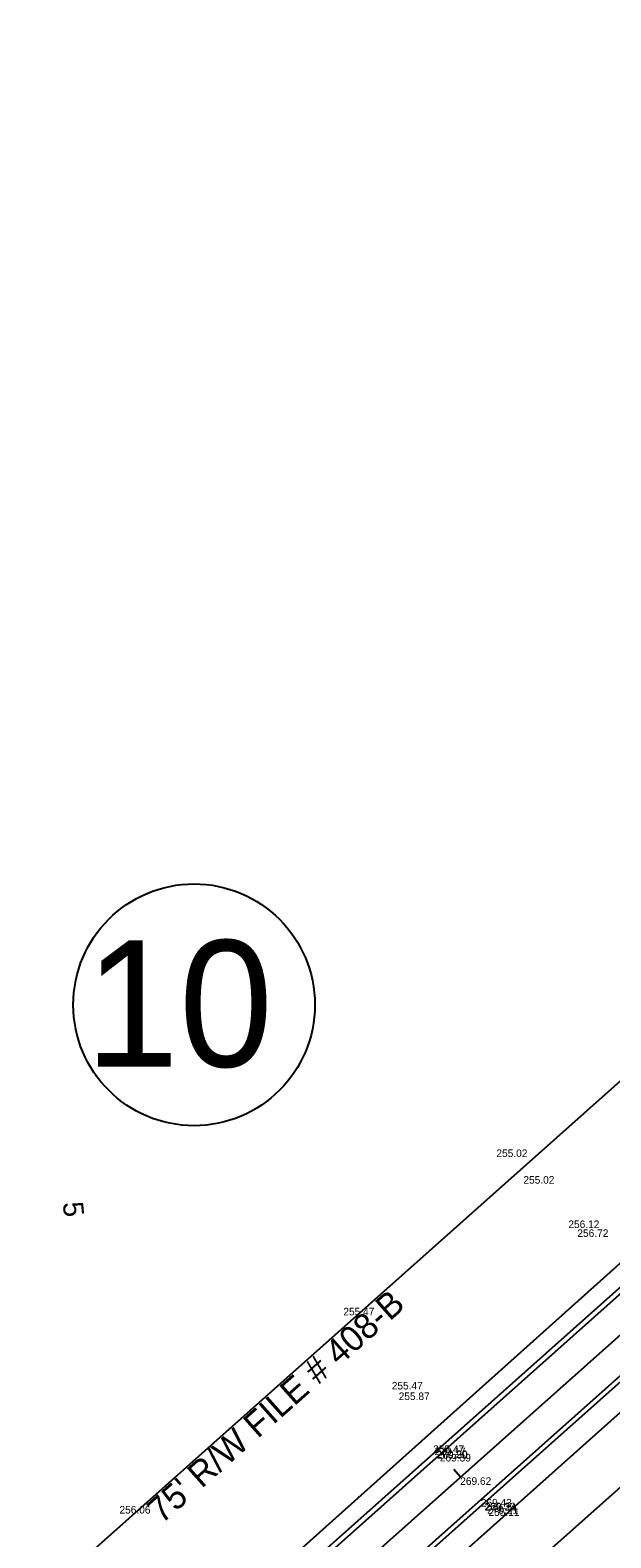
# Model space of a CAD drawing. Extents: x 49683 to 58852, y 49525 to 54803.
# Drawn here: x 53645 to 53875, y 51789 to 52385 of the extents above; entities that cross this region are included whole.
import ezdxf

# ---------------------------------------------------------------- set-up
doc = ezdxf.new("R2010")
doc.units = 0
for name, color, linetype in [('Level 1', 7, 'Continuous'), ('Level 11', 7, 'Continuous'), ('Level 13', 7, 'Continuous'), ('Level 15', 7, 'Continuous'), ('Level 19', 7, 'Continuous'), ('Level 21', 7, 'Continuous'), ('Level 25', 7, 'Continuous'), ('Level 3', 7, 'Continuous'), ('Level 32', 7, 'Continuous'), ('Level 5', 7, 'Continuous')]:
    doc.layers.add(name, color=color, linetype=linetype)

msp = doc.modelspace()

# ---------------------------------------------------------------- linework, layer by layer
at = {"layer": 'Level 1'}
for p, q in [((52544.81, 50683.3), (55534.58, 53340.86)), ((53815.54, 51812.83), (53812.88, 51815.82))]:
    msp.add_line(p, q, dxfattribs=at)
at = {"layer": 'Level 11'}
msp.add_line((53424.49, 51490.93), (53894.91, 51911.93), dxfattribs=at)
at = {"layer": 'Level 13'}
msp.add_line((53573.51, 51698.05), (53897.28, 51985.83), dxfattribs=at)
at = {"layer": 'Level 15'}
msp.add_line((53460.73, 51466.68), (53909.18, 51865.3), dxfattribs=at)
at = {"layer": 'Level 19'}
msp.add_line((52714.15, 50773.62), (54181.77, 52078.16), dxfattribs=at)
at = {"layer": 'Level 25'}
msp.add_circle((53710.13, 51999.57), 47.8, dxfattribs=at)
at = {"layer": 'Level 3'}
for p, q in [((53434.09, 51489.84), (53883.27, 51889.18)), ((53449.72, 51471.81), (53898.74, 51870.57))]:
    msp.add_line(p, q, dxfattribs=at)
at = {"layer": 'Level 5'}
for p, q in [((53432.56, 51491.2), (53881.99, 51890.68)), ((53900.07, 51869.4), (53451.19, 51470.16))]:
    msp.add_line(p, q, dxfattribs=at)

# ---------------------------------------------------------------- texts
at = {"layer": 'Level 21'}
msp.add_text('5', height=8, rotation=275.86038, dxfattribs=at).set_placement((53658.15, 51921.29))
at = {"layer": 'Level 25'}
msp.add_text('10', height=50, dxfattribs=at).set_placement((53667, 51975.08))
msp.add_text("75' R/W FILE # 408-B", height=10, rotation=41.63333, dxfattribs=at).set_placement((53697.32, 51794.05))
at = {"layer": 'Level 32'}
for s, p in [('255.02', (53829.8, 51939.38)), ('255.02', (53840.48, 51928.84)), ('256.12', (53858.28, 51911.29)), ('256.72', (53861.84, 51907.78)), ('255.47', (53769.22, 51876.76)), ('255.47', (53788.37, 51847.46)), ('255.87', (53791.11, 51843.28)), ('255.47', (53804.78, 51822.35)), ('270.17', (53805.33, 51821.52)), ('270.20', (53806.06, 51820.4)), ('269.30', (53806.2, 51820.12)), ('269.39', (53807.42, 51818.99)), ('269.62', (53815.47, 51809.74)), ('256.06', (53680.61, 51798.4)), ('269.43', (53823.62, 51801.19)), ('269.33', (53825.11, 51799.69)), ('270.24', (53825.3, 51799.49)), ('270.21', (53826.09, 51798.3)), ('255.11', (53826.64, 51797.47))]:
    msp.add_text(s, height=3, dxfattribs=at).set_placement(p)

doc.saveas('drawing.dxf')
